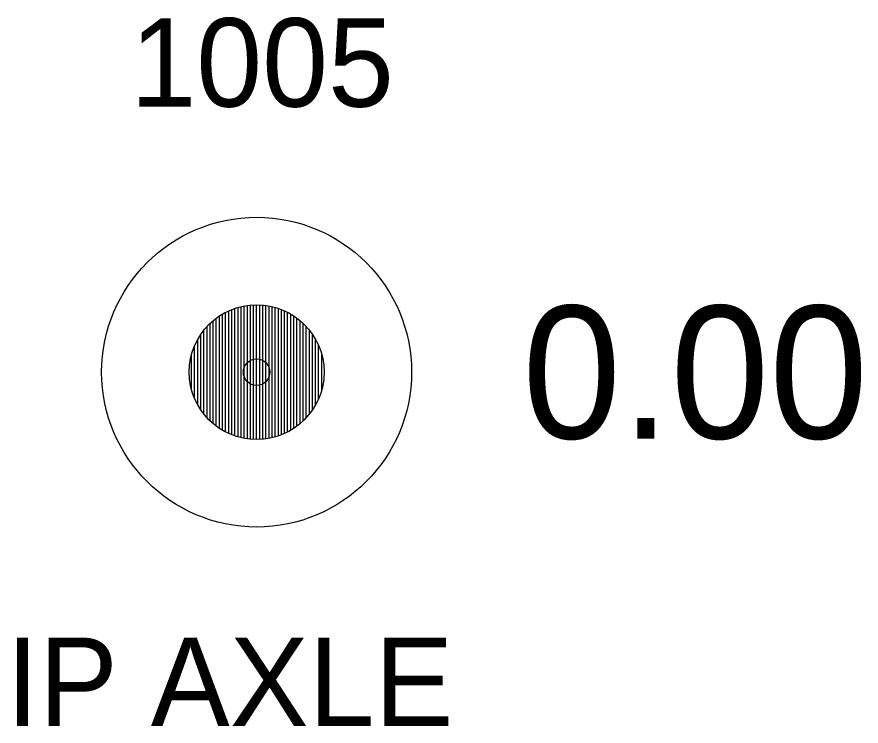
# Model space of a CAD drawing. Extents: x 1664393 to 1667175, y 987029 to 988607.
# Drawn here: x 1666411.32 to 1666420.85, y 987028.77 to 987036.79 of the extents above; entities that cross this region are included whole.
import ezdxf

# ---------------------------------------------------------------- set-up
doc = ezdxf.new("R2010")
doc.units = 0
for name, color, linetype in [('RD_EX_DV_Prop_txCode', 7, 'Continuous'), ('RD_EX_DV_PropPin', 7, 'Continuous'), ('RD_EX_TX_DV_Prop_ELEV', 7, 'Continuous'), ('RD_SMD_Locator', 7, 'Continuous')]:
    doc.layers.add(name, color=color, linetype=linetype)

msp = doc.modelspace()

# ---------------------------------------------------------------- linework, layer by layer
at = {"layer": 'RD_EX_DV_PropPin'}
for p, q in [((1666413.7458, 987032.0644), (1666413.7458, 987033.4796)), ((1666413.7808, 987032.0515), (1666413.7808, 987033.4925)), ((1666413.8158, 987032.0406), (1666413.8158, 987033.5034)), ((1666413.8508, 987032.0314), (1666413.8508, 987033.5126)), ((1666413.8858, 987032.024), (1666413.8858, 987033.52)), ((1666413.9208, 987032.0183), (1666413.9208, 987033.5257)), ((1666413.9559, 987032.0142), (1666413.9559, 987033.5298)), ((1666413.9909, 987032.0118), (1666413.9909, 987033.5322)), ((1666414.0259, 987032.011), (1666414.0259, 987033.533)), ((1666414.0609, 987032.0118), (1666414.0609, 987033.5322)), ((1666414.0959, 987032.0142), (1666414.0959, 987033.5298)), ((1666414.1309, 987032.0183), (1666414.1309, 987033.5257)), ((1666414.1659, 987032.024), (1666414.1659, 987033.52)), ((1666414.2009, 987032.0314), (1666414.2009, 987033.5126)), ((1666414.236, 987032.0406), (1666414.236, 987033.5034)), ((1666414.271, 987032.0515), (1666414.271, 987033.4925)), ((1666414.306, 987032.0644), (1666414.306, 987033.4796)), ((1666413.5707, 987032.1621), (1666413.5707, 987033.3819)), ((1666413.6057, 987032.1375), (1666413.6057, 987033.4065)), ((1666413.6407, 987032.1156), (1666413.6407, 987033.4284)), ((1666413.6757, 987032.0963), (1666413.6757, 987033.4477)), ((1666413.7108, 987032.0793), (1666413.7108, 987033.4647)), ((1666414.341, 987032.0793), (1666414.341, 987033.4647)), ((1666414.376, 987032.0963), (1666414.376, 987033.4477)), ((1666414.411, 987032.1156), (1666414.411, 987033.4284)), ((1666414.446, 987032.1375), (1666414.446, 987033.4065)), ((1666414.4811, 987032.1621), (1666414.4811, 987033.3819)), ((1666413.4657, 987032.2569), (1666413.4657, 987033.2871)), ((1666413.5007, 987032.2213), (1666413.5007, 987033.3227)), ((1666413.5357, 987032.1899), (1666413.5357, 987033.3541)), ((1666414.5161, 987032.1899), (1666414.5161, 987033.3541)), ((1666414.5511, 987032.2213), (1666414.5511, 987033.3227)), ((1666414.5861, 987032.2569), (1666414.5861, 987033.2871)), ((1666413.3956, 987032.3455), (1666413.3956, 987033.1985)), ((1666413.4306, 987032.2978), (1666413.4306, 987033.2462)), ((1666414.6211, 987032.2978), (1666414.6211, 987033.2462)), ((1666414.6561, 987032.3455), (1666414.6561, 987033.1985)), ((1666413.3606, 987032.4025), (1666413.3606, 987033.1415)), ((1666414.6911, 987032.4025), (1666414.6911, 987033.1415)), ((1666413.3256, 987032.4741), (1666413.3256, 987033.0699)), ((1666414.7262, 987032.4741), (1666414.7262, 987033.0699)), ((1666413.2906, 987032.5758), (1666413.2906, 987032.9682)), ((1666414.7612, 987032.5758), (1666414.7612, 987032.9682))]:
    msp.add_line(p, q, dxfattribs=at)
for radius in [1.75, 0.761]:
    msp.add_circle((1666414.0259, 987032.772), radius, dxfattribs=at)
at = {"layer": 'RD_SMD_Locator'}
msp.add_circle((1666414.0259, 987032.772), 0.15, dxfattribs=at)

# ---------------------------------------------------------------- texts
at = {"layer": 'RD_EX_DV_Prop_txCode'}
for s, p in [('1005', (1666412.6007, 987035.772)), ('IP AXLE', (1666411.1952, 987028.772))]:
    msp.add_text(s, height=1, dxfattribs=at).set_placement(p)
at = {"layer": 'RD_EX_TX_DV_Prop_ELEV'}
msp.add_text('0.00', height=1.5, dxfattribs=at).set_placement((1666417.0259, 987032.022))

doc.saveas('drawing.dxf')
